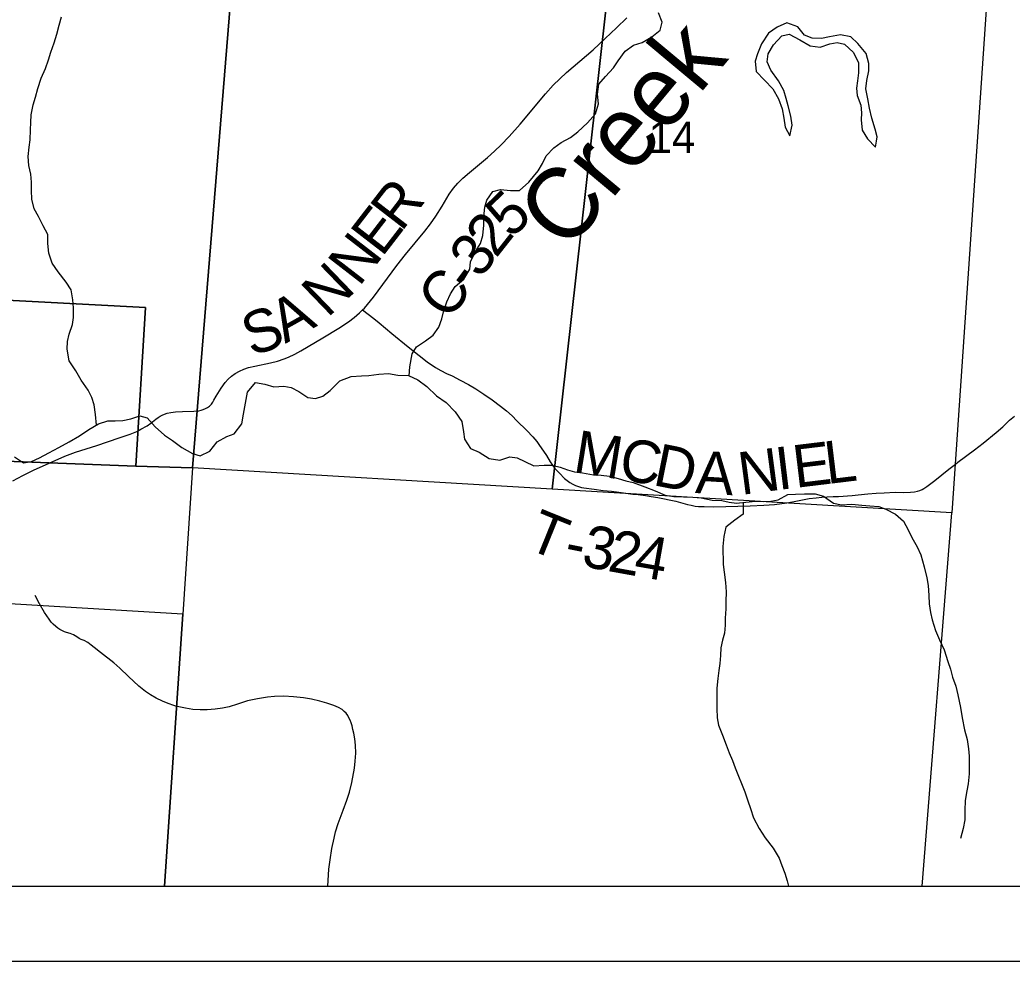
# Model space of a CAD drawing. Extents: x 0 to 34, y 0 to 22.
# Drawn here: x 6.999 to 8.324, y 14 to 15.257 of the extents above; entities that cross this region are included whole.
import ezdxf

# ---------------------------------------------------------------- set-up
doc = ezdxf.new("R2010")
doc.units = 0
for name, color, linetype in [('GM_X_Corporation', 7, 'Continuous'), ('GM_X_County_Road', 7, 'Continuous'), ('GM_X_County_Road_Text', 7, 'Continuous'), ('GM_X_Minor_Lake', 7, 'Continuous'), ('GM_X_Minor_River', 7, 'Continuous'), ('GM_X_Minor_River_Text', 7, 'Continuous'), ('GM_X_Section_Text', 7, 'Continuous'), ('GM_X_Township_Road', 7, 'Continuous'), ('GM_X_Township_Road_Text', 7, 'Continuous'), ('SH_Data', 7, 'Continuous')]:
    doc.layers.add(name, color=color, linetype=linetype)

msp = doc.modelspace()

# ---------------------------------------------------------------- linework, layer by layer
at = {"layer": 'GM_X_Corporation'}
for points in [[(7.3098, 15.6422), (7.2299, 14.6588), (7.1543, 14.6607), (7.1673, 14.8728), (6.654, 14.8997), (6.7101, 15.6799)], [(7.8195, 15.6086), (7.7098, 14.6303), (7.2299, 14.6588), (7.3098, 15.6422)], [(8.3102, 15.5772), (8.2437, 14.5985), (7.7098, 14.6303), (7.8195, 15.6086)], [(6.654, 14.8997), (7.1673, 14.8728), (7.1543, 14.6607), (6.2382, 14.6961), (6.2563, 14.9189)], [(6.2382, 14.6961), (7.1543, 14.6607), (7.2299, 14.6588), (7.2168, 14.4634), (6.2242, 14.5225)], [(7.1924, 14.1), (8.2041, 14.1), (8.2437, 14.5985), (7.7098, 14.6303), (7.2299, 14.6588), (7.2168, 14.4634)], [(6.2243, 14.1), (7.1924, 14.1), (7.2168, 14.4634), (6.2242, 14.5225), (6.1902, 14.1019)]]:
    msp.add_lwpolyline(points, close=True, dxfattribs=at)
at = {"layer": 'GM_X_County_Road'}
msp.add_lwpolyline([(6.9898, 14.6414), (7.0035, 14.6486), (7.0174, 14.6554), (7.0596, 14.6743), (7.0737, 14.6797), (7.1023, 14.6887), (7.132, 14.6985), (7.1467, 14.7037), (7.1554, 14.7073), (7.161, 14.7101), (7.1691, 14.7149), (7.1742, 14.7185), (7.181, 14.7238), (7.184, 14.726), (7.1866, 14.7275), (7.1892, 14.7289), (7.1925, 14.7304), (7.1961, 14.7315), (7.201, 14.7326), (7.2073, 14.7333), (7.2164, 14.7338), (7.2318, 14.7342), (7.2381, 14.7348), (7.2412, 14.7355), (7.2442, 14.7365), (7.2471, 14.7377), (7.2498, 14.7393), (7.2526, 14.7412), (7.255, 14.7438), (7.2568, 14.7464), (7.2583, 14.749), (7.2616, 14.7543), (7.268, 14.765), (7.2734, 14.7725), (7.2774, 14.7772), (7.2819, 14.7812), (7.2869, 14.7846), (7.2926, 14.7879), (7.2982, 14.7904), (7.3048, 14.7927), (7.3129, 14.7943), (7.3341, 14.799), (7.3432, 14.8013), (7.3521, 14.8042), (7.3579, 14.8065), (7.3663, 14.8106), (7.3746, 14.815), (7.404, 14.8323), (7.4252, 14.8452), (7.4382, 14.8537), (7.4457, 14.8593), (7.4529, 14.8654), (7.4569, 14.8694), (7.4595, 14.872), (7.4636, 14.8767), (7.4714, 14.8864), (7.5028, 14.9289), (7.5141, 14.9436), (7.5398, 14.9747), (7.5474, 14.9846), (7.5546, 14.9948), (7.563, 15.0079), (7.5727, 15.0239), (7.5782, 15.0319), (7.5841, 15.0387), (7.5907, 15.0452), (7.5998, 15.0532), (7.6236, 15.0732), (7.6329, 15.0814), (7.642, 15.0899), (7.6527, 15.1012), (7.6671, 15.1175), (7.701, 15.1579), (7.7114, 15.1694), (7.7201, 15.1782), (7.7292, 15.1865), (7.7647, 15.2168), (7.7806, 15.2317), (7.7958, 15.246), (7.8097, 15.2593)], dxfattribs=at)
at = {"layer": 'GM_X_Minor_Lake'}
for p, q in [((8.0234, 15.2527), (8.0102, 15.2469)), ((8.0379, 15.2475), (8.0234, 15.2527)), ((7.9986, 15.2392), (7.9893, 15.2247)), ((8.0102, 15.2469), (7.9986, 15.2392)), ((8.0055, 15.2233), (8.0164, 15.2356)), ((8.0164, 15.2356), (8.0266, 15.2376)), ((8.0266, 15.2376), (8.0407, 15.2301)), ((8.0467, 15.2362), (8.0379, 15.2475)), ((8.0573, 15.2325), (8.0467, 15.2362)), ((8.0951, 15.237), (8.0804, 15.2339)), ((8.1087, 15.2341), (8.0951, 15.237)), ((7.9893, 15.2247), (7.9841, 15.2114)), ((7.9984, 15.2112), (8.0055, 15.2233)), ((8.0407, 15.2301), (8.0544, 15.2223)), ((8.0544, 15.2223), (8.068, 15.2205)), ((8.0694, 15.2319), (8.0573, 15.2325)), ((8.068, 15.2205), (8.0808, 15.2248)), ((8.0804, 15.2339), (8.0694, 15.2319)), ((8.0808, 15.2248), (8.0906, 15.2264)), ((8.0906, 15.2264), (8.1001, 15.2242)), ((8.1001, 15.2242), (8.1123, 15.2133)), ((8.1183, 15.2251), (8.1087, 15.2341)), ((8.1294, 15.212), (8.1183, 15.2251)), ((7.9841, 15.2114), (7.9808, 15.2015)), ((7.997, 15.2009), (7.9984, 15.2112)), ((8.1123, 15.2133), (8.1189, 15.1994)), ((8.1329, 15.1984), (8.1294, 15.212)), ((7.9808, 15.2015), (7.9824, 15.1879)), ((8.002, 15.1896), (7.997, 15.2009)), ((8.1189, 15.1994), (8.119, 15.1861)), ((8.1326, 15.1885), (8.1329, 15.1984)), ((7.9824, 15.1879), (8.0045, 15.1646)), ((8.012, 15.1753), (8.002, 15.1896)), ((8.119, 15.1861), (8.1176, 15.1755)), ((8.13, 15.176), (8.1326, 15.1885)), ((8.0193, 15.1625), (8.012, 15.1753)), ((8.1176, 15.1755), (8.1161, 15.1656)), ((8.1286, 15.1646), (8.13, 15.176)), ((8.0045, 15.1646), (8.0122, 15.1514)), ((8.0224, 15.1519), (8.0193, 15.1625)), ((8.1161, 15.1656), (8.1174, 15.1558)), ((8.1174, 15.1558), (8.122, 15.1429)), ((8.1314, 15.1514), (8.1286, 15.1646)), ((8.0122, 15.1514), (8.0169, 15.1378)), ((8.0252, 15.142), (8.0224, 15.1519)), ((8.122, 15.1429), (8.1232, 15.1327)), ((8.1338, 15.1389), (8.1314, 15.1514)), ((8.0169, 15.1378), (8.0192, 15.1257)), ((8.0287, 15.1281), (8.0252, 15.142)), ((8.1232, 15.1327), (8.1226, 15.1232)), ((8.1369, 15.1253), (8.1338, 15.1389)), ((8.0192, 15.1257), (8.0209, 15.1136)), ((8.0274, 15.1019), (8.0303, 15.1163)), ((8.0303, 15.1163), (8.0287, 15.1281)), ((8.1226, 15.1232), (8.1238, 15.1096)), ((8.1412, 15.1109), (8.1369, 15.1253)), ((8.0209, 15.1136), (8.0274, 15.1019)), ((8.1238, 15.1096), (8.1311, 15.0979)), ((8.1439, 15.1007), (8.1412, 15.1109)), ((8.1311, 15.0979), (8.1418, 15.0867)), ((8.1418, 15.0867), (8.1431, 15.095)), ((8.1431, 15.095), (8.1439, 15.1007))]:
    msp.add_line(p, q, dxfattribs=at)
at = {"layer": 'GM_X_Minor_River'}
for p, q in [((7.0485, 15.2377), (7.0518, 15.2499)), ((7.0518, 15.2499), (7.0551, 15.2609)), ((7.0452, 15.226), (7.0485, 15.2377)), ((7.0408, 15.2138), (7.0452, 15.226)), ((7.0378, 15.2035), (7.0408, 15.2138)), ((7.0338, 15.1917), (7.0378, 15.2035)), ((7.0278, 15.1788), (7.0338, 15.1917)), ((7.0234, 15.1651), (7.0278, 15.1788)), ((7.0201, 15.1537), (7.0234, 15.1651)), ((7.0146, 15.1298), (7.0172, 15.1435)), ((7.0172, 15.1435), (7.0201, 15.1537)), ((7.014, 15.1199), (7.0146, 15.1298)), ((7.0137, 15.1101), (7.014, 15.1199)), ((7.013, 15.0968), (7.0137, 15.1101)), ((7.012, 15.087), (7.013, 15.0968)), ((7.0106, 15.0744), (7.012, 15.087)), ((7.0114, 15.0623), (7.0106, 15.0744)), ((7.0138, 15.0506), (7.0114, 15.0623)), ((7.015, 15.04), (7.0138, 15.0506)), ((7.0148, 15.029), (7.015, 15.04)), ((7.0152, 15.0173), (7.0148, 15.029)), ((7.0184, 15.0044), (7.0152, 15.0173)), ((7.0241, 14.9942), (7.0184, 15.0044)), ((7.0303, 14.9818), (7.0241, 14.9942)), ((7.0368, 14.9701), (7.0303, 14.9818)), ((7.0369, 14.958), (7.0368, 14.9701)), ((7.0382, 14.9451), (7.0369, 14.958)), ((7.0425, 14.9319), (7.0382, 14.9451)), ((7.0505, 14.9202), (7.0425, 14.9319)), ((7.0612, 14.9066), (7.0505, 14.9202)), ((7.0678, 14.8961), (7.0612, 14.9066)), ((7.0701, 14.8829), (7.0678, 14.8961)), ((7.071, 14.8723), (7.0701, 14.8829)), ((7.0711, 14.8594), (7.071, 14.8723)), ((7.0697, 14.8499), (7.0711, 14.8594)), ((7.0652, 14.8373), (7.0697, 14.8499)), ((7.0624, 14.8172), (7.0631, 14.8275)), ((7.0631, 14.8275), (7.0652, 14.8373)), ((7.0652, 14.8017), (7.0624, 14.8172)), ((7.074, 14.7882), (7.0652, 14.8017)), ((7.0813, 14.7757), (7.074, 14.7882)), ((7.0905, 14.7625), (7.0813, 14.7757)), ((7.0955, 14.7527), (7.0905, 14.7625)), ((7.0986, 14.7429), (7.0955, 14.7527)), ((7.1002, 14.73), (7.0986, 14.7429)), ((7.1019, 14.7157), (7.1002, 14.73)), ((7.9652, 14.6126), (7.9652, 14.5966)), ((7.9539, 14.5889), (7.9419, 14.5793)), ((7.9652, 14.5966), (7.9539, 14.5889)), ((7.9419, 14.5793), (7.939, 14.5672)), ((7.939, 14.5672), (7.938, 14.5535)), ((7.938, 14.5535), (7.9382, 14.5296)), ((7.9382, 14.5296), (7.9398, 14.5194)), ((7.9398, 14.5194), (7.9414, 14.5054)), ((7.9414, 14.5054), (7.9423, 14.4929)), ((7.942, 14.4804), (7.9417, 14.4702)), ((7.9423, 14.4929), (7.942, 14.4804)), ((7.9417, 14.4702), (7.9411, 14.458)), ((7.9411, 14.458), (7.9408, 14.4486)), ((7.9408, 14.4486), (7.9401, 14.4379)), ((7.9375, 14.4284), (7.935, 14.4182)), ((7.9401, 14.4379), (7.9375, 14.4284)), ((7.935, 14.4182), (7.9347, 14.4083)), ((7.9347, 14.4083), (7.934, 14.3973)), ((7.9326, 14.3879), (7.9312, 14.3776)), ((7.934, 14.3973), (7.9326, 14.3879)), ((7.9312, 14.3776), (7.9298, 14.3643)), ((7.9298, 14.3643), (7.93, 14.3374)), ((7.93, 14.3374), (7.9305, 14.3249)), ((7.9305, 14.3249), (7.9321, 14.3151)), ((7.9321, 14.3151), (7.9375, 14.3019)), ((7.9375, 14.3019), (7.9422, 14.289)), ((7.9422, 14.289), (7.9464, 14.2781)), ((7.9464, 14.2781), (7.9507, 14.2679)), ((7.9507, 14.2679), (7.9542, 14.2581)), ((7.9542, 14.2581), (7.9673, 14.226)), ((7.9673, 14.226), (7.9712, 14.2139)), ((7.9712, 14.2139), (7.9747, 14.2037)), ((7.9747, 14.2037), (7.9786, 14.1912)), ((7.9786, 14.1912), (7.9863, 14.1773)), ((7.9863, 14.1773), (7.9943, 14.1645)), ((7.9943, 14.1645), (8.005, 14.1509)), ((8.005, 14.1509), (8.0131, 14.1373)), ((8.0131, 14.1373), (8.0166, 14.1275)), ((8.0166, 14.1275), (8.0208, 14.1173)), ((8.0208, 14.1173), (8.0236, 14.1071)), ((8.0236, 14.1071), (8.0254, 14.1))]:
    msp.add_line(p, q, dxfattribs=at)
for points in [[(7.5192, 14.7815), (7.52, 14.7934), (7.5229, 14.8108), (7.5289, 14.8203), (7.5409, 14.8284), (7.5511, 14.8357), (7.5586, 14.8464), (7.5626, 14.8578), (7.5655, 14.8688), (7.5692, 14.8802), (7.5741, 14.8909), (7.5804, 14.9008), (7.592, 14.9107), (7.5999, 14.9241), (7.6009, 14.9339), (7.6076, 14.9476), (7.6143, 14.9583), (7.6173, 14.9689), (7.619, 14.9826), (7.6189, 14.994), (7.6203, 15.0065), (7.6229, 15.016), (7.6308, 15.0278), (7.641, 15.0302), (7.6546, 15.0288), (7.6663, 15.0289), (7.6787, 15.04), (7.6911, 15.0553), (7.697, 15.0652), (7.7022, 15.0751), (7.7124, 15.0858), (7.7221, 15.0931), (7.7346, 15.0996), (7.7443, 15.1073), (7.7571, 15.1191), (7.768, 15.1314), (7.772, 15.1447), (7.7704, 15.1575), (7.7722, 15.1708), (7.7811, 15.1811), (7.792, 15.1926), (7.798, 15.2021), (7.8073, 15.2151), (7.8186, 15.2232), (7.8303, 15.2267), (7.8431, 15.234), (7.854, 15.2432), (7.8569, 15.2538), (7.8519, 15.2663)], [(6.9921, 14.6733), (7.0043, 14.6655), (7.0149, 14.6671), (7.0254, 14.6721), (7.0382, 14.6787), (7.0514, 14.686), (7.065, 14.6933), (7.0789, 14.7014), (7.0913, 14.7099), (7.1045, 14.7172), (7.1166, 14.7215), (7.1268, 14.7212), (7.137, 14.7217), (7.1476, 14.724), (7.1596, 14.7283), (7.1691, 14.7254), (7.1802, 14.7133), (7.1924, 14.7021), (7.2031, 14.695), (7.2156, 14.686), (7.2297, 14.6778), (7.2399, 14.6748), (7.2531, 14.681), (7.2629, 14.6932), (7.2757, 14.7006), (7.2855, 14.7041), (7.2959, 14.7174), (7.2981, 14.7303), (7.2999, 14.7402), (7.3013, 14.7501), (7.3032, 14.7595), (7.314, 14.7725), (7.3265, 14.7704), (7.3383, 14.7667), (7.3519, 14.7679), (7.3617, 14.7658), (7.3716, 14.7605), (7.3838, 14.7527), (7.394, 14.7513), (7.4038, 14.7544), (7.4136, 14.7617), (7.4264, 14.7747), (7.4418, 14.7805), (7.4554, 14.7814), (7.4653, 14.7819), (7.4785, 14.7835), (7.4917, 14.7844), (7.5039, 14.7826), (7.5182, 14.782), (7.5308, 14.776), (7.5426, 14.7674), (7.5556, 14.755), (7.5685, 14.7457), (7.5807, 14.7333), (7.5892, 14.7205), (7.5915, 14.7068), (7.5928, 14.697), (7.6008, 14.6846), (7.6126, 14.6794), (7.6259, 14.6712), (7.6403, 14.669), (7.6535, 14.6733), (7.6634, 14.6719), (7.6736, 14.6671), (7.6854, 14.6615), (7.6994, 14.6624), (7.7096, 14.6621), (7.7206, 14.6595), (7.7305, 14.6558), (7.74, 14.6533), (7.7506, 14.6518), (7.7653, 14.6493), (7.7756, 14.6487), (7.7865, 14.6476), (7.7979, 14.6443), (7.8082, 14.6414), (7.818, 14.6392), (7.8336, 14.6333)], [(7.8336, 14.6333), (7.8476, 14.6281), (7.8609, 14.6221), (7.8723, 14.6204), (7.8855, 14.6201), (7.8977, 14.6195), (7.909, 14.6184), (7.9238, 14.6155), (7.9363, 14.6149), (7.9461, 14.6127), (7.956, 14.6117), (7.9685, 14.6129), (7.9813, 14.6142), (7.9919, 14.6135), (8.0018, 14.614), (8.0116, 14.6159), (8.0248, 14.6229), (8.035, 14.6234), (8.0471, 14.6238), (8.0611, 14.624), (8.0721, 14.6207), (8.0858, 14.6113), (8.0964, 14.6091), (8.11, 14.61), (8.1233, 14.609), (8.1339, 14.608), (8.146, 14.6069), (8.1555, 14.6036), (8.1684, 14.5969), (8.1791, 14.5875), (8.1852, 14.5758), (8.1902, 14.5657), (8.1971, 14.5532), (8.2022, 14.5427), (8.2065, 14.5264), (8.2104, 14.5117), (8.212, 14.5014), (8.2128, 14.4882), (8.2133, 14.4772), (8.2153, 14.4655), (8.2173, 14.4556), (8.2216, 14.4413), (8.227, 14.4288), (8.2332, 14.4156), (8.2382, 14.4001), (8.2417, 14.3899), (8.2444, 14.379), (8.2487, 14.3672), (8.2518, 14.3555), (8.255, 14.3385), (8.2574, 14.3249), (8.2606, 14.309), (8.2641, 14.2958), (8.2657, 14.2837), (8.2665, 14.2738), (8.2668, 14.2499), (8.2654, 14.2367), (8.2635, 14.2272), (8.2614, 14.2143), (8.2611, 14.201), (8.2609, 14.1889), (8.2587, 14.1771), (8.255, 14.1638)]]:
    msp.add_lwpolyline(points, dxfattribs=at)
at = {"layer": 'GM_X_Township_Road'}
for points in [[(7.4569, 14.8694), (7.4643, 14.8637), (7.4719, 14.858), (7.479, 14.8523), (7.496, 14.838), (7.5178, 14.8203), (7.5326, 14.8087), (7.5433, 14.8002), (7.5541, 14.7927), (7.5614, 14.7884), (7.5691, 14.7848), (7.5765, 14.7814), (7.5874, 14.7758), (7.5982, 14.77), (7.6083, 14.764), (7.6189, 14.757), (7.6298, 14.7493), (7.6412, 14.7412), (7.6492, 14.7349), (7.6566, 14.728), (7.6629, 14.7215), (7.676, 14.7086), (7.684, 14.7001), (7.6895, 14.6936), (7.6931, 14.6883), (7.6984, 14.6809), (7.7023, 14.6752), (7.7073, 14.6665), (7.7136, 14.6579), (7.7196, 14.6514), (7.7266, 14.6445), (7.7335, 14.6391), (7.7376, 14.6368), (7.7412, 14.6351), (7.7437, 14.6342), (7.745, 14.6337), (7.7492, 14.6326), (7.7524, 14.6321), (7.7663, 14.6301), (7.7783, 14.6286), (7.7894, 14.6273), (7.7992, 14.626), (7.8082, 14.6248), (7.8175, 14.6236), (7.8246, 14.6229), (7.8348, 14.6216), (7.8424, 14.6205), (7.8511, 14.6189), (7.8599, 14.6173), (7.8661, 14.6161), (7.875, 14.6142), (7.8844, 14.6117), (7.8906, 14.6098), (7.8954, 14.6086), (7.9008, 14.6077), (7.9052, 14.6072), (7.913, 14.6069), (7.9254, 14.6068), (7.9743, 14.6081), (7.9928, 14.6087), (8.0067, 14.6098), (8.0235, 14.6119), (8.033, 14.6137), (8.0442, 14.616), (8.0533, 14.6176), (8.0626, 14.6187), (8.0699, 14.6194), (8.0773, 14.6198), (8.0851, 14.6203), (8.0923, 14.6206), (8.1107, 14.6217), (8.1184, 14.6226), (8.1314, 14.624), (8.1427, 14.6247), (8.1534, 14.6253), (8.1678, 14.626), (8.1795, 14.6259), (8.1886, 14.6261), (8.1938, 14.6267), (8.1977, 14.6276), (8.2008, 14.6286), (8.2038, 14.6298), (8.2063, 14.6312), (8.2103, 14.6337), (8.2207, 14.6417), (8.2396, 14.6568), (8.2483, 14.6637), (8.2514, 14.6662), (8.2737, 14.6827), (8.2856, 14.6915), (8.3026, 14.7058), (8.3118, 14.7134), (8.3207, 14.7221), (8.3274, 14.7278)], [(7.4103, 14.1), (7.4119, 14.1227), (7.4136, 14.1355), (7.416, 14.1504), (7.4188, 14.1642), (7.4208, 14.1727), (7.4243, 14.1838), (7.4268, 14.1911), (7.431, 14.2018), (7.4359, 14.2148), (7.4393, 14.2258), (7.4425, 14.2384), (7.4459, 14.2577), (7.4471, 14.2671), (7.4479, 14.2779), (7.4476, 14.2882), (7.4466, 14.297), (7.4452, 14.3043), (7.4441, 14.3094), (7.4428, 14.3141), (7.4415, 14.3181), (7.4402, 14.3217), (7.4386, 14.325), (7.437, 14.3279), (7.4349, 14.331), (7.4325, 14.3335), (7.4297, 14.3359), (7.4248, 14.3387), (7.4186, 14.3413), (7.4094, 14.3444), (7.3998, 14.3472), (7.3888, 14.3496), (7.3779, 14.3515), (7.3648, 14.3531), (7.3519, 14.3536), (7.3393, 14.3533), (7.33, 14.3524), (7.3166, 14.3504), (7.3032, 14.3474), (7.2897, 14.3433), (7.2786, 14.3397), (7.2698, 14.3377), (7.2599, 14.3363), (7.2492, 14.3354), (7.2401, 14.3355), (7.2302, 14.3362), (7.2206, 14.3376), (7.2114, 14.3396), (7.2077, 14.3406), (7.205, 14.3414), (7.1973, 14.344), (7.1899, 14.347), (7.1814, 14.3513), (7.1738, 14.3557), (7.1673, 14.3602), (7.1583, 14.3673), (7.1443, 14.3801), (7.1327, 14.391), (7.1247, 14.3984), (7.1068, 14.4123), (7.0985, 14.419), (7.0947, 14.4221), (7.0899, 14.4255), (7.0854, 14.4281), (7.0814, 14.4295), (7.0786, 14.4309), (7.0756, 14.4329), (7.071, 14.4355), (7.0664, 14.4374), (7.0618, 14.4388), (7.0589, 14.4399), (7.0555, 14.4415), (7.0528, 14.443), (7.0502, 14.4447), (7.0473, 14.447), (7.044, 14.4499), (7.0413, 14.4528), (7.0385, 14.4566), (7.0322, 14.4655), (7.0254, 14.477), (7.02, 14.4884)]]:
    msp.add_lwpolyline(points, dxfattribs=at)
at = {"layer": 'SH_Data'}
for p, q in [((2.1, 14.1), (8.9, 14.1)), ((2, 14), (9, 14))]:
    msp.add_line(p, q, dxfattribs=at)

# ---------------------------------------------------------------- texts
at = {"layer": 'GM_X_County_Road_Text'}
for s, rotation, p in [('R', 52.3277, (7.5087, 14.9726)), ('5', 44.0579, (7.6552, 14.9636)), ('E', 52.3323, (7.4827, 14.9389)), ('2', 51.8425, (7.635, 14.9376)), ('N', 52.3117, (7.4522, 14.8994)), ('3', 52.8845, (7.614, 14.9099)), ('N', 43.961, (7.4101, 14.8579)), ('C', 53.2472, (7.5721, 14.854)), ('-', 53.152, (7.6, 14.8913)), ('A', 29.1261, (7.3536, 14.824)), ('S', 20.1946, (7.3088, 14.8068))]:
    msp.add_text(s, height=0.0568, rotation=rotation, dxfattribs=at).set_placement(p)
at = {"layer": 'GM_X_Minor_River_Text'}
msp.add_text('Creek', height=0.0947, rotation=50.172, dxfattribs=at).set_placement((7.7301, 14.9452))
at = {"layer": 'GM_X_Section_Text'}
msp.add_text('14', height=0.04186, rotation=0, dxfattribs=at).set_placement((7.8388, 15.0791))
at = {"layer": 'GM_X_Township_Road_Text'}
for s, rotation, p in [('M', 350.7746, (7.7365, 14.6533)), ('C', 350.7456, (7.7974, 14.6434)), ('E', 6.9209, (8.0348, 14.6318)), ('L', 6.9252, (8.077, 14.6369)), ('D', 348.6293, (7.8429, 14.636)), ('A', 356.5077, (7.9004, 14.6251)), ('N', 7.5683, (7.9623, 14.6224)), ('I', 6.9256, (8.0117, 14.629)), ('T', 337.959, (7.6737, 14.5518)), ('3', 349.1828, (7.7476, 14.5279)), ('2', 349.7936, (7.7826, 14.5212)), ('4', 349.9605, (7.8173, 14.5149)), ('-', 348.6818, (7.7242, 14.5326))]:
    msp.add_text(s, height=0.0568, rotation=rotation, dxfattribs=at).set_placement(p)

doc.saveas('drawing.dxf')
